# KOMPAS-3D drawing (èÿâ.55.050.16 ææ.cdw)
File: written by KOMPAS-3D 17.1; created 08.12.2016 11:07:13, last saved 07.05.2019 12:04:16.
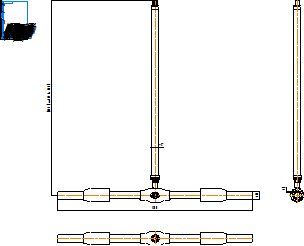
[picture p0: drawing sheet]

Sheet 1: A4, portrait

Title block, sheet 1: name: КШГ.55.050.16 СС; material: Внимание! Данный продукт является объектом авторского права ООО «Торговый Дом АДЛ». / Запрещается изменение, копирование, распространение / (в том числе путем копирования на другие сайты и ресурсы в Интернете) / или любое иное использование информации и объектов без предварительного / согласия правообладателя (ООО «Торговый Дом АДЛ»).; sheets: 1; organisation: ООО "Торговый дом АДЛ"; sheet format: A4; stored path: C:\Users\kka\KOMPAS_Work\Модели кранов для исследований\DN65\С удлинением\КШГ.35.050.25 СС ГЧ _ Шаровой кран БИВАЛ Ду50 Ру2,5 МПа полнопроходной под приварку, c удлинением штока H=950 Габаритный чертеж Lстр600.cdw; drawn by: Климкович К.А.; drawn by, date: 07.12.16

Views: Вид 1, Проекционный вид 2
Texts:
  Klimkovich
  ADL
  (от 287 до 5000)
Dimensions and other numbers on the sheet: 1500; 57; 63; 7,1; 1:1; 1; 07.12.16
